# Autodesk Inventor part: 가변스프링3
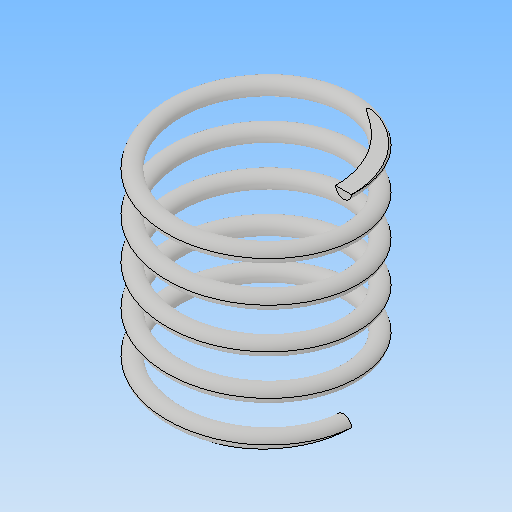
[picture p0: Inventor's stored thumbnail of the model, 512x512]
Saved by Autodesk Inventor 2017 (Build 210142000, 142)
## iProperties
Part Number: 가변스프링3
Material: 일반
Document SubType Name: Modeling
Designer: MRC
Density: 1 g/cm^3
Appearance: 기본값
Mass: 1.06675 g
Surface Area: 21.6501 cm^2
Volume: 1.06675 cm^3
Author: MRC
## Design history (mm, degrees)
sketch "스케치1"
  geometry: L1 (0, 0)-(0, 25.358); L2 (0, 0)-(11, 0); L3 (0, 25.358)-(11, 25.358); C1 r 1 at (11, 0)
  constraints: 6 end point, 2 horizontal, 1 centre point, 1 coincident, 1 vertical
  dimensions: "d0" = 25.35829 distance of L1.start L1.end (derived); "d1" = 11 distance of L1.start L2.end; "d2" = 2 diameter of C1
feature "코일1" pitch "d3" = 10; turns "d5" = 5; dims "d4" = 25.35829 (= d0), "d6" = 0, angle "d7" = 90 deg, angle "d8" = 90 deg, "d9" = 0, "d10" = 0
sketch "스케치2"
  geometry: L1 (25.358, 15)-(0, 15); L2 (0, 15)-(0, -15); L3 (0, -15)-(25.358, -15); L4 (25.358, -15)-(25.358, 15); 2 further points
  constraints: 8 end point, 2 parallel, 1 coincident, 1 horizontal, 1 midpoint, 1 perpendicular
  dimensions: "d11" = 30 distance of L3.end L1.start; "d12" = 25.35829 distance of L2.end L3.end (= d0)
extrude "돌출1" sketch "스케치2" stored distance "d13" = 30; taper "d14" = 0 deg
node "솔리드1"
